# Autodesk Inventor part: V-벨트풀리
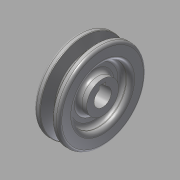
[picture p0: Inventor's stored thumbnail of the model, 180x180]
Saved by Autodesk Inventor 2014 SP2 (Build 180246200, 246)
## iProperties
Created: 2015-12
Part Number: V-벨트풀리
Material: 강철, 연강
Document SubType Name: Modeling
Designer: mduedu
Density: 7.86 g/cm^3
Appearance: 강철
Author: mduedu
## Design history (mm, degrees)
sketch "스케치1"
  geometry: L1 (-9.5, 0)-(9.5, 0); L2 (-9.5, 0)-(-9.5, 32.7); L3 (-9.5, 32.7)-(-4.825, 32.7); L4 (-4.825, 32.7)-(-2.074, 23.7); L5 (-2.074, 23.7)-(0, 23.7); L6 (0, 0)-(0, 23.7); L7 (9.5, 0)-(9.5, 32.7); L8 (9.5, 32.7)-(4.825, 32.7); L9 (4.825, 32.7)-(2.074, 23.7); L10 (2.074, 23.7)-(0, 23.7); L11 (-4, 30)-(4, 30); 3 further points
  constraints: 22 end point, 3 coincident, 3 perpendicular, 3 symmetric about line, 2 parallel, 2 point on line, 1 horizontal, 1 midpoint, 1 vertical alignment
  dimensions: "d0" = 19 distance between parallel lines of L7 L2; "d2" = 6.3 distance between parallel lines of L10 L11; "d3" = 34 deg angle of L9 L4; "d4" = 2.7 distance between parallel lines of L11 L8; "d5" = 60 diameter of L11 L1; "d6" = 8 distance of L11.end L11.start
revolve "회전1" sketch "스케치1" stored, may be unused: angle "d7" = 90 deg
sketch "스케치2"
  geometry: C1 r 21 at (0, 0); C2 r 12 at (0, 0); 1 further point
  constraints: 2 centre point, 2 coincident
  dimensions: "d8" = 42 diameter of C1; "d10" = 24 diameter of C2
extrude "돌출1" cut sketch "스케치2" distance "d11" = 6.5; taper "d12" = 0 deg
fillet "모깎기1" dims "d13" = 1, "d14" = 0.5, "d15" = 2
fillet "모깎기2" dims "d16" = 3
fillet "모깎기3" dims "d17" = 3
hole "구멍1" diameter "d20" = 13; stored, may be unused: countersink angle "d24" = 90 deg, drill point angle "d26" = 118 deg; dims "d18" = 10, "d19" = 10, "d21" = 6, "d22" = 4, "d23" = 2, "d25" = 8
sketch "스케치3"
  geometry: L1 (-2.5, 0)-(2.5, 0); L2 (2.5, 0)-(2.5, 8.8); L3 (2.5, 8.8)-(-2.5, 8.8); L4 (-2.5, 8.8)-(-2.5, 0); 2 further points
  constraints: 8 end point, 2 parallel, 1 coincident, 1 horizontal, 1 midpoint, 1 perpendicular
  dimensions: "d27" = 8.8 distance of L1.end L2.end; "d29" = 5 distance of L2.end L3.end
extrude "돌출2" cut sketch "스케치3" stored distance "d30" = 6.5; taper "d31" = 0 deg
node "솔리드1"
mirror "대칭1"
